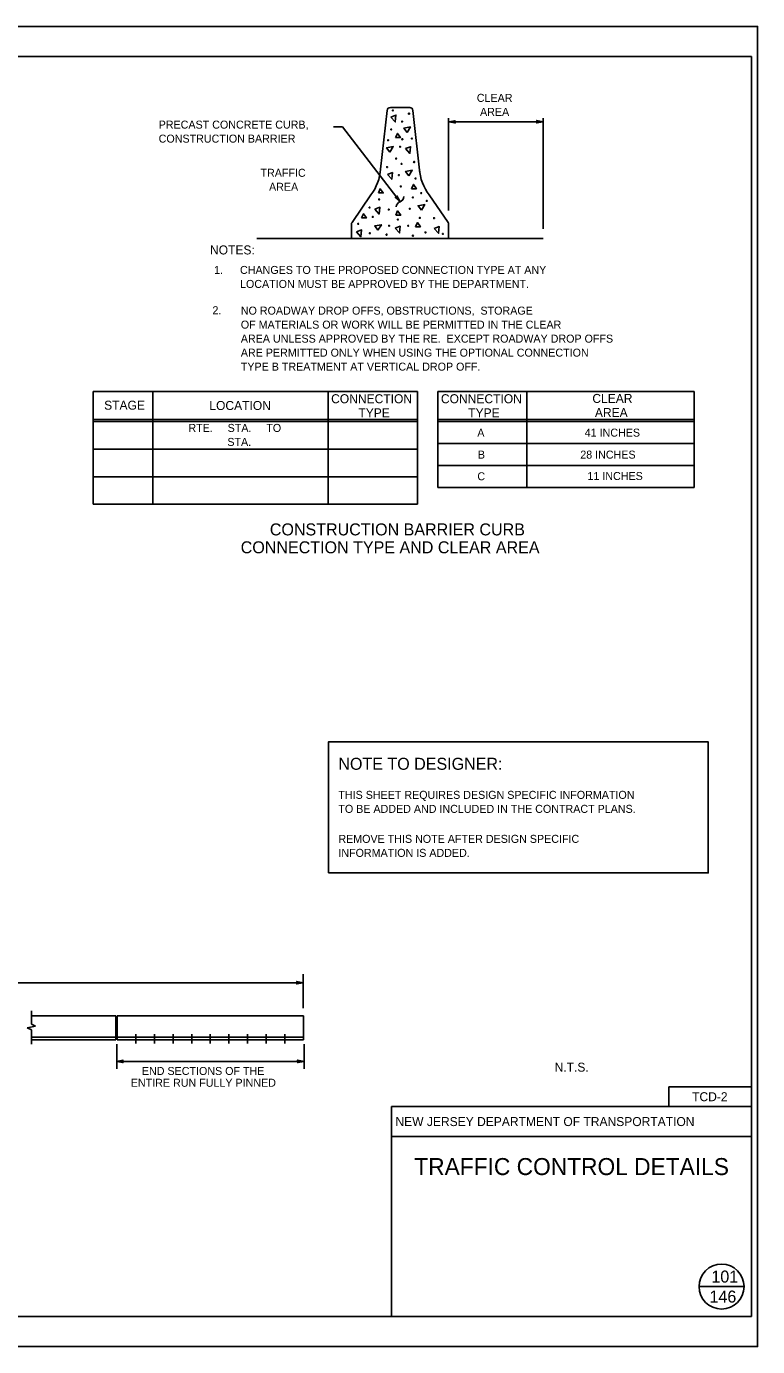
# Model space of a CAD drawing. Extents: x 499909 to 500993, y 502505 to 503165.
# Drawn here: x 500628 to 500993, y 502505 to 503165 of the extents above; entities that cross this region are included whole.
import ezdxf

# ---------------------------------------------------------------- set-up
doc = ezdxf.new("R2010")
doc.units = 0
for name, color, linetype in [('1', 7, 'Continuous'), ('24', 7, 'Continuous'), ('3', 7, 'Continuous'), ('41', 7, 'Continuous'), ('5', 7, 'Continuous'), ('63', 7, 'Continuous')]:
    doc.layers.add(name, color=color, linetype=linetype)

msp = doc.modelspace()

# ---------------------------------------------------------------- linework, layer by layer
at = {"layer": '1'}
for p, q in [((500993, 503165), (499944.83, 503165)), ((500990, 503150), (500000, 503150)), ((500990, 502520), (500990, 503150)), ((500838.59, 503117.3), (500885.83, 503117.3)), ((500742.78, 503058.9), (500885.83, 503058.9)), ((500660.94, 502982.41), (500660.94, 502926.08)), ((500660.94, 502982.41), (500690.8, 502982.41)), ((500690.8, 502982.41), (500690.8, 502926.08)), ((500690.8, 502982.41), (500778.31, 502982.41)), ((500778.31, 502982.41), (500778.31, 502926.08)), ((500778.31, 502982.41), (500823.03, 502982.41)), ((500823.03, 502982.41), (500823.03, 502926.08)), ((500833.23, 502982.41), (500961.31, 502982.41)), ((500833.23, 502982.41), (500833.23, 502934.45)), ((500877.74, 502982.41), (500877.74, 502934.45)), ((500961.31, 502982.41), (500961.31, 502934.45)), ((500660.94, 502968.42), (500823.03, 502968.42)), ((500660.94, 502967.42), (500823.03, 502967.42)), ((500833.23, 502968.42), (500961.31, 502968.42)), ((500833.23, 502967.42), (500961.31, 502967.42)), ((500660.94, 502953.64), (500823.03, 502953.64)), ((500833.23, 502956.43), (500961.31, 502956.43)), ((500660.94, 502939.86), (500823.03, 502939.86)), ((500833.23, 502945.44), (500961.31, 502945.44)), ((500833.23, 502934.45), (500961.31, 502934.45)), ((500660.94, 502926.08), (500823.03, 502926.08)), ((500990, 502634.84), (500948.66, 502634.84)), ((500948.66, 502634.84), (500948.66, 502625)), ((500990, 502625), (500810, 502625)), ((500810, 502625), (500810, 502520)), ((500990, 502610), (500810, 502610)), ((500975, 502535), (500963.75, 502535)), ((500975, 502535), (500986.25, 502535)), ((500000, 502520), (500990, 502520)), ((500993, 502505), (499944.83, 502505))]:
    msp.add_line(p, q, dxfattribs=at)
msp.add_lwpolyline([(500778.48, 502741.83), (500968.31, 502741.83), (500968.31, 502807.31), (500778.48, 502807.31)], close=True, dxfattribs=at)
msp.add_circle((500975, 502535), 11.25, dxfattribs=at)
at = {"layer": '24'}
for points in [[(500838.59, 503117.3), (500841.86, 503116.72), (500841.08, 503117.3), (500841.84, 503117.87), (500838.59, 503117.3), (500838.8, 503117.31), (500841.77, 503116.77), (500841.02, 503117.31), (500841.71, 503117.83), (500838.92, 503117.32), (500839.03, 503117.3), (500841.57, 503116.85), (500841, 503117.31), (500841.59, 503117.75), (500839.08, 503117.3), (500839.19, 503117.32), (500841.41, 503116.92), (500840.98, 503117.3), (500841.42, 503117.7), (500839.51, 503117.32), (500839.69, 503117.32), (500841.24, 503117), (500840.94, 503117.29), (500841.27, 503117.62), (500839.72, 503117.3), (500839.9, 503117.29), (500841.07, 503117.09), (500840.84, 503117.32), (500841.09, 503117.54), (500840.06, 503117.3), (500840.22, 503117.29), (500840.93, 503117.15), (500840.81, 503117.31), (500841, 503117.49), (500840.31, 503117.3), (500840.77, 503117.19), (500840.7, 503117.32), (500840.9, 503117.45), (500840.42, 503117.32), (500840.72, 503117.24), (500840.6, 503117.34), (500840.74, 503117.4), (500840.6, 503117.31), (500840.67, 503117.29)], [(500885.83, 503117.3), (500882.56, 503117.88), (500883.34, 503117.3), (500882.57, 503116.73), (500885.83, 503117.3), (500885.61, 503117.3), (500882.65, 503117.84), (500883.4, 503117.3), (500882.71, 503116.78), (500885.5, 503117.29), (500885.39, 503117.3), (500882.85, 503117.76), (500883.42, 503117.3), (500882.83, 503116.85), (500885.34, 503117.3), (500885.23, 503117.29), (500883.01, 503117.69), (500883.44, 503117.3), (500883, 503116.9), (500884.91, 503117.29), (500884.73, 503117.29), (500883.17, 503117.61), (500883.48, 503117.31), (500883.15, 503116.99), (500884.69, 503117.3), (500884.52, 503117.31), (500883.35, 503117.51), (500883.58, 503117.29), (500883.33, 503117.06), (500884.36, 503117.3), (500884.19, 503117.32), (500883.49, 503117.45), (500883.61, 503117.3), (500883.42, 503117.12), (500884.11, 503117.3), (500883.65, 503117.41), (500883.72, 503117.29), (500883.52, 503117.16), (500883.99, 503117.29), (500883.69, 503117.36), (500883.82, 503117.26), (500883.67, 503117.2), (500883.82, 503117.3), (500883.74, 503117.31)], [(500814.31, 503077.33), (500812.77, 503080.28), (500812.79, 503079.31), (500811.87, 503079.57), (500814.31, 503077.33), (500814.17, 503077.5), (500812.79, 503080.18), (500812.82, 503079.26), (500811.99, 503079.49), (500814.09, 503077.59), (500814.03, 503077.69), (500812.85, 503079.98), (500812.83, 503079.24), (500812.12, 503079.44), (500814, 503077.73), (500813.93, 503077.8), (500812.89, 503079.81), (500812.85, 503079.23), (500812.26, 503079.34), (500813.73, 503078.05), (500813.62, 503078.2), (500812.93, 503079.63), (500812.88, 503079.21), (500812.42, 503079.27), (500813.61, 503078.24), (500813.51, 503078.38), (500812.96, 503079.43), (500812.92, 503079.11), (500812.59, 503079.17), (500813.41, 503078.5), (500813.32, 503078.64), (500813, 503079.28), (500812.95, 503079.09), (500812.69, 503079.14), (500813.26, 503078.7), (500813.06, 503079.13), (500813, 503079), (500812.78, 503079.08), (500813.17, 503078.78), (500813.05, 503079.07), (500813.05, 503078.91), (500812.91, 503078.98), (500813.07, 503078.93), (500813.04, 503079)], [(500765.89, 502686.89), (500762.57, 502687.48), (500763.36, 502686.89), (500762.59, 502686.31), (500765.89, 502686.89), (500765.67, 502686.88), (500762.66, 502687.43), (500763.43, 502686.88), (500762.72, 502686.36), (500765.55, 502686.87), (500765.44, 502686.89), (500762.86, 502687.35), (500763.44, 502686.88), (500762.85, 502686.43), (500765.39, 502686.89), (500765.28, 502686.87), (500763.03, 502687.28), (500763.47, 502686.89), (500763.02, 502686.48), (500764.96, 502686.87), (500764.77, 502686.87), (500763.2, 502687.2), (500763.5, 502686.9), (500763.17, 502686.57), (500764.74, 502686.89), (500764.56, 502686.9), (500763.38, 502687.1), (500763.6, 502686.87), (500763.36, 502686.64), (500764.4, 502686.89), (500764.23, 502686.91), (500763.52, 502687.04), (500763.64, 502686.88), (500763.44, 502686.7), (500764.15, 502686.89), (500763.68, 502687), (500763.75, 502686.87), (500763.54, 502686.75), (500764.03, 502686.87), (500763.72, 502686.95), (500763.85, 502686.85), (500763.71, 502686.79), (500763.85, 502686.88), (500763.77, 502686.9)], [(500672.6, 502647.58), (500675.92, 502646.99), (500675.13, 502647.58), (500675.91, 502648.16), (500672.6, 502647.58), (500672.82, 502647.59), (500675.83, 502647.04), (500675.07, 502647.59), (500675.77, 502648.11), (500672.94, 502647.6), (500673.05, 502647.58), (500675.63, 502647.12), (500675.05, 502647.59), (500675.64, 502648.04), (500673.1, 502647.58), (500673.21, 502647.6), (500675.46, 502647.19), (500675.03, 502647.58), (500675.47, 502647.98), (500673.53, 502647.6), (500673.72, 502647.6), (500675.3, 502647.27), (500674.99, 502647.57), (500675.32, 502647.9), (500673.75, 502647.58), (500673.93, 502647.57), (500675.12, 502647.37), (500674.89, 502647.6), (500675.14, 502647.82), (500674.09, 502647.58), (500674.26, 502647.56), (500674.97, 502647.43), (500674.86, 502647.59), (500675.05, 502647.76), (500674.35, 502647.58), (500674.81, 502647.47), (500674.74, 502647.6), (500674.95, 502647.72), (500674.46, 502647.6), (500674.77, 502647.52), (500674.64, 502647.62), (500674.79, 502647.68), (500674.64, 502647.59), (500674.72, 502647.57)], [(500766.38, 502647.58), (500763.05, 502648.17), (500763.85, 502647.58), (500763.07, 502647), (500766.38, 502647.58), (500766.16, 502647.57), (500763.15, 502648.12), (500763.91, 502647.57), (500763.21, 502647.05), (500766.04, 502647.56), (500765.93, 502647.58), (500763.35, 502648.04), (500763.93, 502647.57), (500763.33, 502647.12), (500765.88, 502647.58), (500765.77, 502647.56), (500763.51, 502647.97), (500763.95, 502647.58), (500763.5, 502647.17), (500765.45, 502647.56), (500765.26, 502647.56), (500763.68, 502647.89), (500763.99, 502647.59), (500763.66, 502647.26), (500765.23, 502647.58), (500765.05, 502647.59), (500763.86, 502647.79), (500764.09, 502647.56), (500763.84, 502647.33), (500764.88, 502647.58), (500764.72, 502647.6), (500764, 502647.73), (500764.12, 502647.57), (500763.93, 502647.39), (500764.63, 502647.58), (500764.17, 502647.69), (500764.23, 502647.56), (500764.03, 502647.44), (500764.51, 502647.56), (500764.21, 502647.64), (500764.34, 502647.54), (500764.19, 502647.48), (500764.34, 502647.57), (500764.26, 502647.59)]]:
    msp.add_lwpolyline(points, dxfattribs=at)
for centre, start, end in [((500813.41, 503079.95), 288.80041, 359.1656), ((500815.2, 503074.71), 108.80041, 179.1656)]:
    msp.add_arc(centre, 2.77, start, end, dxfattribs=at)
at = {"layer": '3'}
for p, q in [((500807.85, 503123.03), (500804.59, 503093.71)), ((500809.46, 503124.46), (500819.15, 503124.46)), ((500820.76, 503123.03), (500824.25, 503091.65)), ((500799.74, 503080.76), (500790.31, 503067.02)), ((500828.87, 503080.76), (500838.3, 503067.02)), ((500790.02, 503058.9), (500790.02, 503066.11)), ((500838.59, 503058.9), (500838.59, 503066.11)), ((500838.59, 503058.9), (500790.02, 503058.9)), ((500073.16, 502686.89), (500765.89, 502686.89)), ((500630.08, 502666.2), (500630.08, 502672.89)), ((500672.25, 502670.39), (500630.08, 502670.39)), ((500672.25, 502670.39), (500672.25, 502668.24)), ((500673, 502670.39), (500765.99, 502670.39)), ((500673, 502670.39), (500673, 502668.24)), ((500765.99, 502670.39), (500765.99, 502668.24)), ((500632.19, 502665.12), (500627.94, 502664.36)), ((500627.94, 502664.36), (500630.08, 502663.41)), ((500630.08, 502666.2), (500632.19, 502665.12)), ((500630.08, 502663.41), (500630.08, 502656.15)), ((500672.25, 502668.24), (500672.25, 502658.4)), ((500673, 502668.24), (500673, 502658.4)), ((500765.99, 502668.24), (500765.99, 502658.4)), ((500672.28, 502659.62), (500630.08, 502659.62)), ((500672.25, 502658.4), (500630.08, 502658.4)), ((500672.97, 502659.62), (500765.99, 502659.62)), ((500673, 502658.4), (500765.99, 502658.4)), ((500682.3, 502661.16), (500682.3, 502656.45)), ((500691.6, 502661.16), (500691.6, 502656.45)), ((500700.9, 502661.16), (500700.9, 502656.45)), ((500710.19, 502661.16), (500710.19, 502656.45)), ((500719.49, 502661.16), (500719.49, 502656.45)), ((500728.79, 502661.16), (500728.79, 502656.45)), ((500738.09, 502661.16), (500738.09, 502656.45)), ((500747.39, 502661.16), (500747.39, 502656.45)), ((500756.68, 502661.16), (500756.68, 502656.45)), ((500672.6, 502647.58), (500766.38, 502647.58))]:
    msp.add_line(p, q, dxfattribs=at)
for centre, radius, start, end in [((500809.46, 503122.84), 1.62, 90, 173.29016), ((500819.15, 503122.84), 1.62, 6.70984, 90), ((500780.55, 503095.34), 24.1, 322.76719, 356.12072), ((500848.06, 503095.34), 24.1, 183.87928, 217.23281), ((500791.64, 503066.11), 1.62, 145.52407, 180), ((500836.97, 503066.11), 1.62, 0, 34.47593)]:
    msp.add_arc(centre, radius, start, end, dxfattribs=at)
at = {"layer": '41'}
for p, q in [((500672.25, 502658.4), (500630.08, 502658.4)), ((500969.33, 502629.92), (500969.33, 502629.92))]:
    msp.add_line(p, q, dxfattribs=at)
msp.add_lwpolyline([(499944.83, 502505), (500993, 502505), (500993, 503165), (499944.83, 503165)], close=True, dxfattribs=at)
at = {"layer": '5'}
for p, q in [((500838.59, 503073.01), (500838.59, 503119.2)), ((500885.83, 503063.84), (500885.83, 503119.2)), ((500785.55, 503114.76), (500781.06, 503114.76)), ((500785.55, 503114.76), (500814.31, 503077.33)), ((500765.89, 502674.24), (500765.89, 502691.19)), ((500672.69, 502643.93), (500672.69, 502656.12)), ((500766.33, 502643.84), (500766.33, 502656.12))]:
    msp.add_line(p, q, dxfattribs=at)
for points in [[(500809.69, 503119.67), (500812.23, 503120.63), (500811.88, 503117.28)], [(500812.08, 503109.43), (500814.49, 503109.43), (500812.98, 503111.54)], [(500817.81, 503111.99), (500816.2, 503114.18), (500819.53, 503114.74)], [(500809.19, 503102.13), (500807.59, 503104.32), (500810.91, 503104.89)], [(500817.07, 503103.91), (500819.61, 503104.86), (500819.26, 503101.51)], [(500807.96, 503090.97), (500810.5, 503091.92), (500810.15, 503088.57)], [(500818.67, 503090.31), (500817.06, 503092.5), (500820.39, 503093.06)], [(500820.07, 503083.86), (500822.48, 503083.86), (500820.97, 503085.97)], [(500803.46, 503081.72), (500805.88, 503081.72), (500804.37, 503083.83)], [(500801.69, 503073.6), (500804.23, 503074.56), (500803.87, 503071.2)], [(500812.2, 503070.63), (500814.62, 503070.63), (500813.11, 503072.74)], [(500824.95, 503073.18), (500823.34, 503075.37), (500826.67, 503075.94)], [(500795.09, 503069.27), (500797.5, 503069.27), (500796, 503071.38)], [(500803.28, 503063.08), (500801.68, 503065.27), (500805, 503065.84)], [(500822.05, 503064.84), (500824.46, 503064.84), (500822.96, 503066.95)], [(500792.58, 503062.27), (500795.12, 503063.22), (500794.76, 503059.87)], [(500811.9, 503064.12), (500814.44, 503065.07), (500814.09, 503061.72)], [(500831.35, 503063.99), (500833.89, 503064.95), (500833.54, 503061.59)]]:
    msp.add_lwpolyline(points, close=True, dxfattribs=at)
for centre in [(500810.77, 503122.97), (500818.78, 503121.37), (500809.91, 503113.49), (500815.33, 503117.43), (500808.31, 503108.06), (500814.34, 503104.86), (500815.45, 503108.56), (500820.25, 503108.93), (500812.37, 503098.95), (500807.82, 503094.64), (500815.08, 503096.24), (500821.36, 503097.22), (500813.73, 503090.7), (500814.71, 503085.03), (500822.1, 503088.97), (500803.88, 503078.5), (500820.75, 503079.49), (500824.93, 503081.7), (500799.08, 503074.43), (500808.68, 503073.45), (500819.15, 503073.82), (500827.64, 503077.76), (500793.42, 503066.3), (500800.68, 503069.75), (500808.8, 503065.32), (500813.24, 503068.4), (500818.41, 503065.32), (500824.19, 503069.26), (500831.33, 503069.14), (500799.2, 503061.62), (500807.57, 503060.88), (500820.75, 503060.39), (500827.02, 503061.99), (500835.76, 503061.25)]:
    msp.add_circle(centre, 0.25, dxfattribs=at)

# ---------------------------------------------------------------- texts
at = {"layer": '1'}
for s, height, p in [('CLEAR', 4, (500852.67, 503127.27)), ('AREA', 4, (500854.29, 503120.27)), ('PRECAST CONCRETE CURB,', 4, (500693.68, 503113.9)), ('CONSTRUCTION BARRIER', 4, (500693.68, 503106.9)), ('TRAFFIC', 4, (500744.57, 503089.81)), ('AREA', 4, (500748.83, 503082.81)), ('NOTES:', 4.5, (500719.33, 503051)), ('1.', 4, (500721.38, 503041.25)), ('CHANGES TO THE PROPOSED CONNECTION TYPE AT ANY', 4, (500734.33, 503041.25)), ('LOCATION MUST BE APPROVED BY THE DEPARTMENT.', 4, (500734.33, 503034.25)), ('2.', 4, (500720.56, 503021.1)), ('NO ROADWAY DROP OFFS, OBSTRUCTIONS,  STORAGE', 4, (500734.73, 503020.91)), ('OF MATERIALS OR WORK WILL BE PERMITTED IN THE CLEAR', 4, (500734.73, 503013.91)), ('AREA UNLESS APPROVED BY THE RE.  EXCEPT ROADWAY DROP OFFS', 4, (500734.73, 503006.91)), ('ARE PERMITTED ONLY WHEN USING THE OPTIONAL CONNECTION', 4, (500734.73, 502999.91)), ('TYPE B TREATMENT AT VERTICAL DROP OFF.  ', 4, (500734.73, 502992.91)), ('CONNECTION', 4.5, (500779.86, 502976.61)), ('CONNECTION', 4.5, (500834.74, 502976.61)), ('CLEAR', 4.5, (500910.42, 502976.76)), ('TYPE', 4.5, (500793.5, 502969.55)), ('TYPE', 4.5, (500848.38, 502969.55)), ('AREA', 4.5, (500911.69, 502969.7)), ('THIS SHEET REQUIRES DESIGN SPECIFIC INFORMATION', 4, (500783.48, 502778.83)), ('TO BE ADDED AND INCLUDED IN THE CONTRACT PLANS.', 4, (500783.48, 502771.83)), ('REMOVE THIS NOTE AFTER DESIGN SPECIFIC ', 4, (500783.48, 502756.83)), ('INFORMATION IS ADDED.', 4, (500783.48, 502749.83)), ('END SECTIONS OF THE ', 4, (500685.29, 502640.8)), ('N.T.S.', 4.5, (500891.56, 502642.44)), ('ENTIRE RUN FULLY PINNED', 4, (500679.75, 502634.9)), ('TCD-2', 4.5, (500960.28, 502627.67)), ('NEW JERSEY DEPARTMENT OF TRANSPORTATION', 4.5, (500812.02, 502615.25)), ('TRAFFIC CONTROL DETAILS', 8.5, (500821.44, 502590.75))]:
    msp.add_text(s, height=height, dxfattribs=at).set_placement(p)
at = {"layer": '3'}
for s, height, p in [('STAGE', 4.5, (500666.41, 502973.38)), ('LOCATION', 4.5, (500719, 502973.23)), ('146', 6, (500968.97, 502527))]:
    msp.add_text(s, height=height, dxfattribs=at).set_placement(p)
at = {"layer": '5'}
for s, height, p in [('RTE.     STA.     TO', 4, (500708.53, 502962.27)), ('A', 4, (500852.92, 502959.88)), ('41 INCHES', 4, (500906.6, 502959.92)), ('STA.', 4, (500728, 502955.27)), ('B', 4, (500853.21, 502948.93)), ('28 INCHES', 4, (500904.38, 502948.93)), ('C', 4, (500852.95, 502938.09)), ('11 INCHES', 4, (500907.97, 502938.23)), ('CONSTRUCTION BARRIER CURB', 6, (500749.23, 502910.53)), ('CONNECTION TYPE AND CLEAR AREA', 6, (500734.68, 502901.58)), ('NOTE TO DESIGNER:', 6, (500783.48, 502793.36))]:
    msp.add_text(s, height=height, dxfattribs=at).set_placement(p)
at = {"layer": '63'}
msp.add_text('101', height=6, dxfattribs=at).set_placement((500969.92, 502537))

doc.saveas('drawing.dxf')
